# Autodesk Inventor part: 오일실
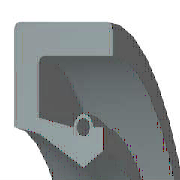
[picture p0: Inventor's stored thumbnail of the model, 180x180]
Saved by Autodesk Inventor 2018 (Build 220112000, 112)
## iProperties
IsCustomPart: 1
Created: 2015-12
Part Number: 오일실
Material: 고무
Description: 오일-실
Document SubType Name: Modeling
Standard: KS B 2804
Designer: mdu
Standards Organization: KS
Language: ko-KR
Size Designation: S - 15 30 7
Categories: <MemberInstance><Categories><Category DisplayName="샤프트 부품" InternalName="7f7aeb1f-a693-4053-b835-cee3144e0d98" Mnemonic="SHFT"><Category DisplayName="실링" Intern
Density: 0.93 g/cm^3
Mass: 1.64364 g
Surface Area: 26.6454 cm^2
Volume: 1.76736 cm^3
Appearance: 고무 - 검은색 - 버전 1.1
Author: mdu
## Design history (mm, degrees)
revolve "본체" stored, may be unused: angle "d17" = 90 deg
revolve "스프링1" stored, may be unused: angle "d18" = 90 deg
body "Solid1"
sketch "스케치1"
  geometry: L1 (0, 15)-(7, 15); L2 (7, 15)-(7, 13.75); L3 (7, 13.75)-(1.75, 13.75); L4 (0, 15)-(0, 9.6); L5 (0, 9.6)-(1.75, 9.25); L6 (1.75, 9.25)-(4.9, 7.5); L7 (4.9, 7.5)-(0, 7.5); L8 (6.3, 8.375)-(6.3, 9.6); L9 (0, 0)-(9.586, 0) reference; L10 (4.9, 7.5)-(6.3, 8.375); L11 (0, 18)-(0, -3) reference; L12 (-1.917, 0)-(11.503, 0) reference; L13 (4.2, 9.6)-(1.75, 10.09); L14 (1.75, 10.09)-(1.75, 13.75); L15 (6.3, 9.6)-(5.6, 9.6); C1 r 0.455 at (4.9, 9.6); A1 r 0.7 centre (4.9, 9.6) between (5.6, 9.6) and (4.2, 9.6)
  constraints: 26 end point, 5 horizontal alignment, 4 perpendicular, 2 centre point, 2 collinear, 2 horizontal, 2 parallel, 2 point on circle, 2 point on line, 2 vertical alignment, 1 coincident
  dimensions: "d0" = 30 diameter of L1 L9 (= SD2); "d1" = 16.75 diameter of L8.start L9 (= ABDM); "d2" = 1.25 distance of L1.end L2.end (computed from SD); "d3" = 0.91 diameter of C1 (= SPDI); "d4" = 1.4 diameter of A1 (= SPDA); "d5" = 15 diameter of L6.end L9 (= NND); "d6" = 18.5 diameter of L5.end L9 (= TKDM); "d7" = 19.2 diameter of L4.end L9 (= HLDM); "d8" = 4.9 distance from line of C1.centre L4 (= SPDST); "d9" = 6.3 distance between parallel lines of L8 L4 (= SDI); "d10" = 7 distance between parallel lines of L2 L4 (= SWDT); "d12" = 1.75 distance between parallel lines of L14 L4 (= SD)
fillet "모깎기1" dims "d11" = 0.3 (= RR)
other parameters: "SD2" = 30 [user parameter; used in 1 equation term], "SWDT" = 7 [user parameter; used in 1 equation term], "RR" = 0.3 [user parameter; used in 1 equation term], "SD" = 1.75 [user parameter; used in 2 equation terms], "NND" = 15 [user parameter; used in 1 equation term], "SPDA" = 1.4 [user parameter; used in 1 equation term], "SPDI" = 0.91 [user parameter; used in 1 equation term], "TKDM" = 18.5 [user parameter; used in 1 equation term], "HLDM" = 19.2 [user parameter; used in 1 equation term], "ABDM" = 16.75 [user parameter; used in 1 equation term], "SDI" = 6.3 [user parameter; used in 1 equation term], "SPDST" = 4.9 [user parameter; used in 1 equation term], "d13" = 0, "d14" = 0, "d15" = 0, "LAB" = 0.35 [user parameter]
